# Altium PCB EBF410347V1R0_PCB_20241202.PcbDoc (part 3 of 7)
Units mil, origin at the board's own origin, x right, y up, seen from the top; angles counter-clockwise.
Board outline 5098.43 x 3464.57 mil, 6 copper layers (TOP, GND02, ART03, ART04, PWR05, BOTTOM), stack 47.2 mil thick; 566 components, 452 nets, 1905 pads, 1432 vias.
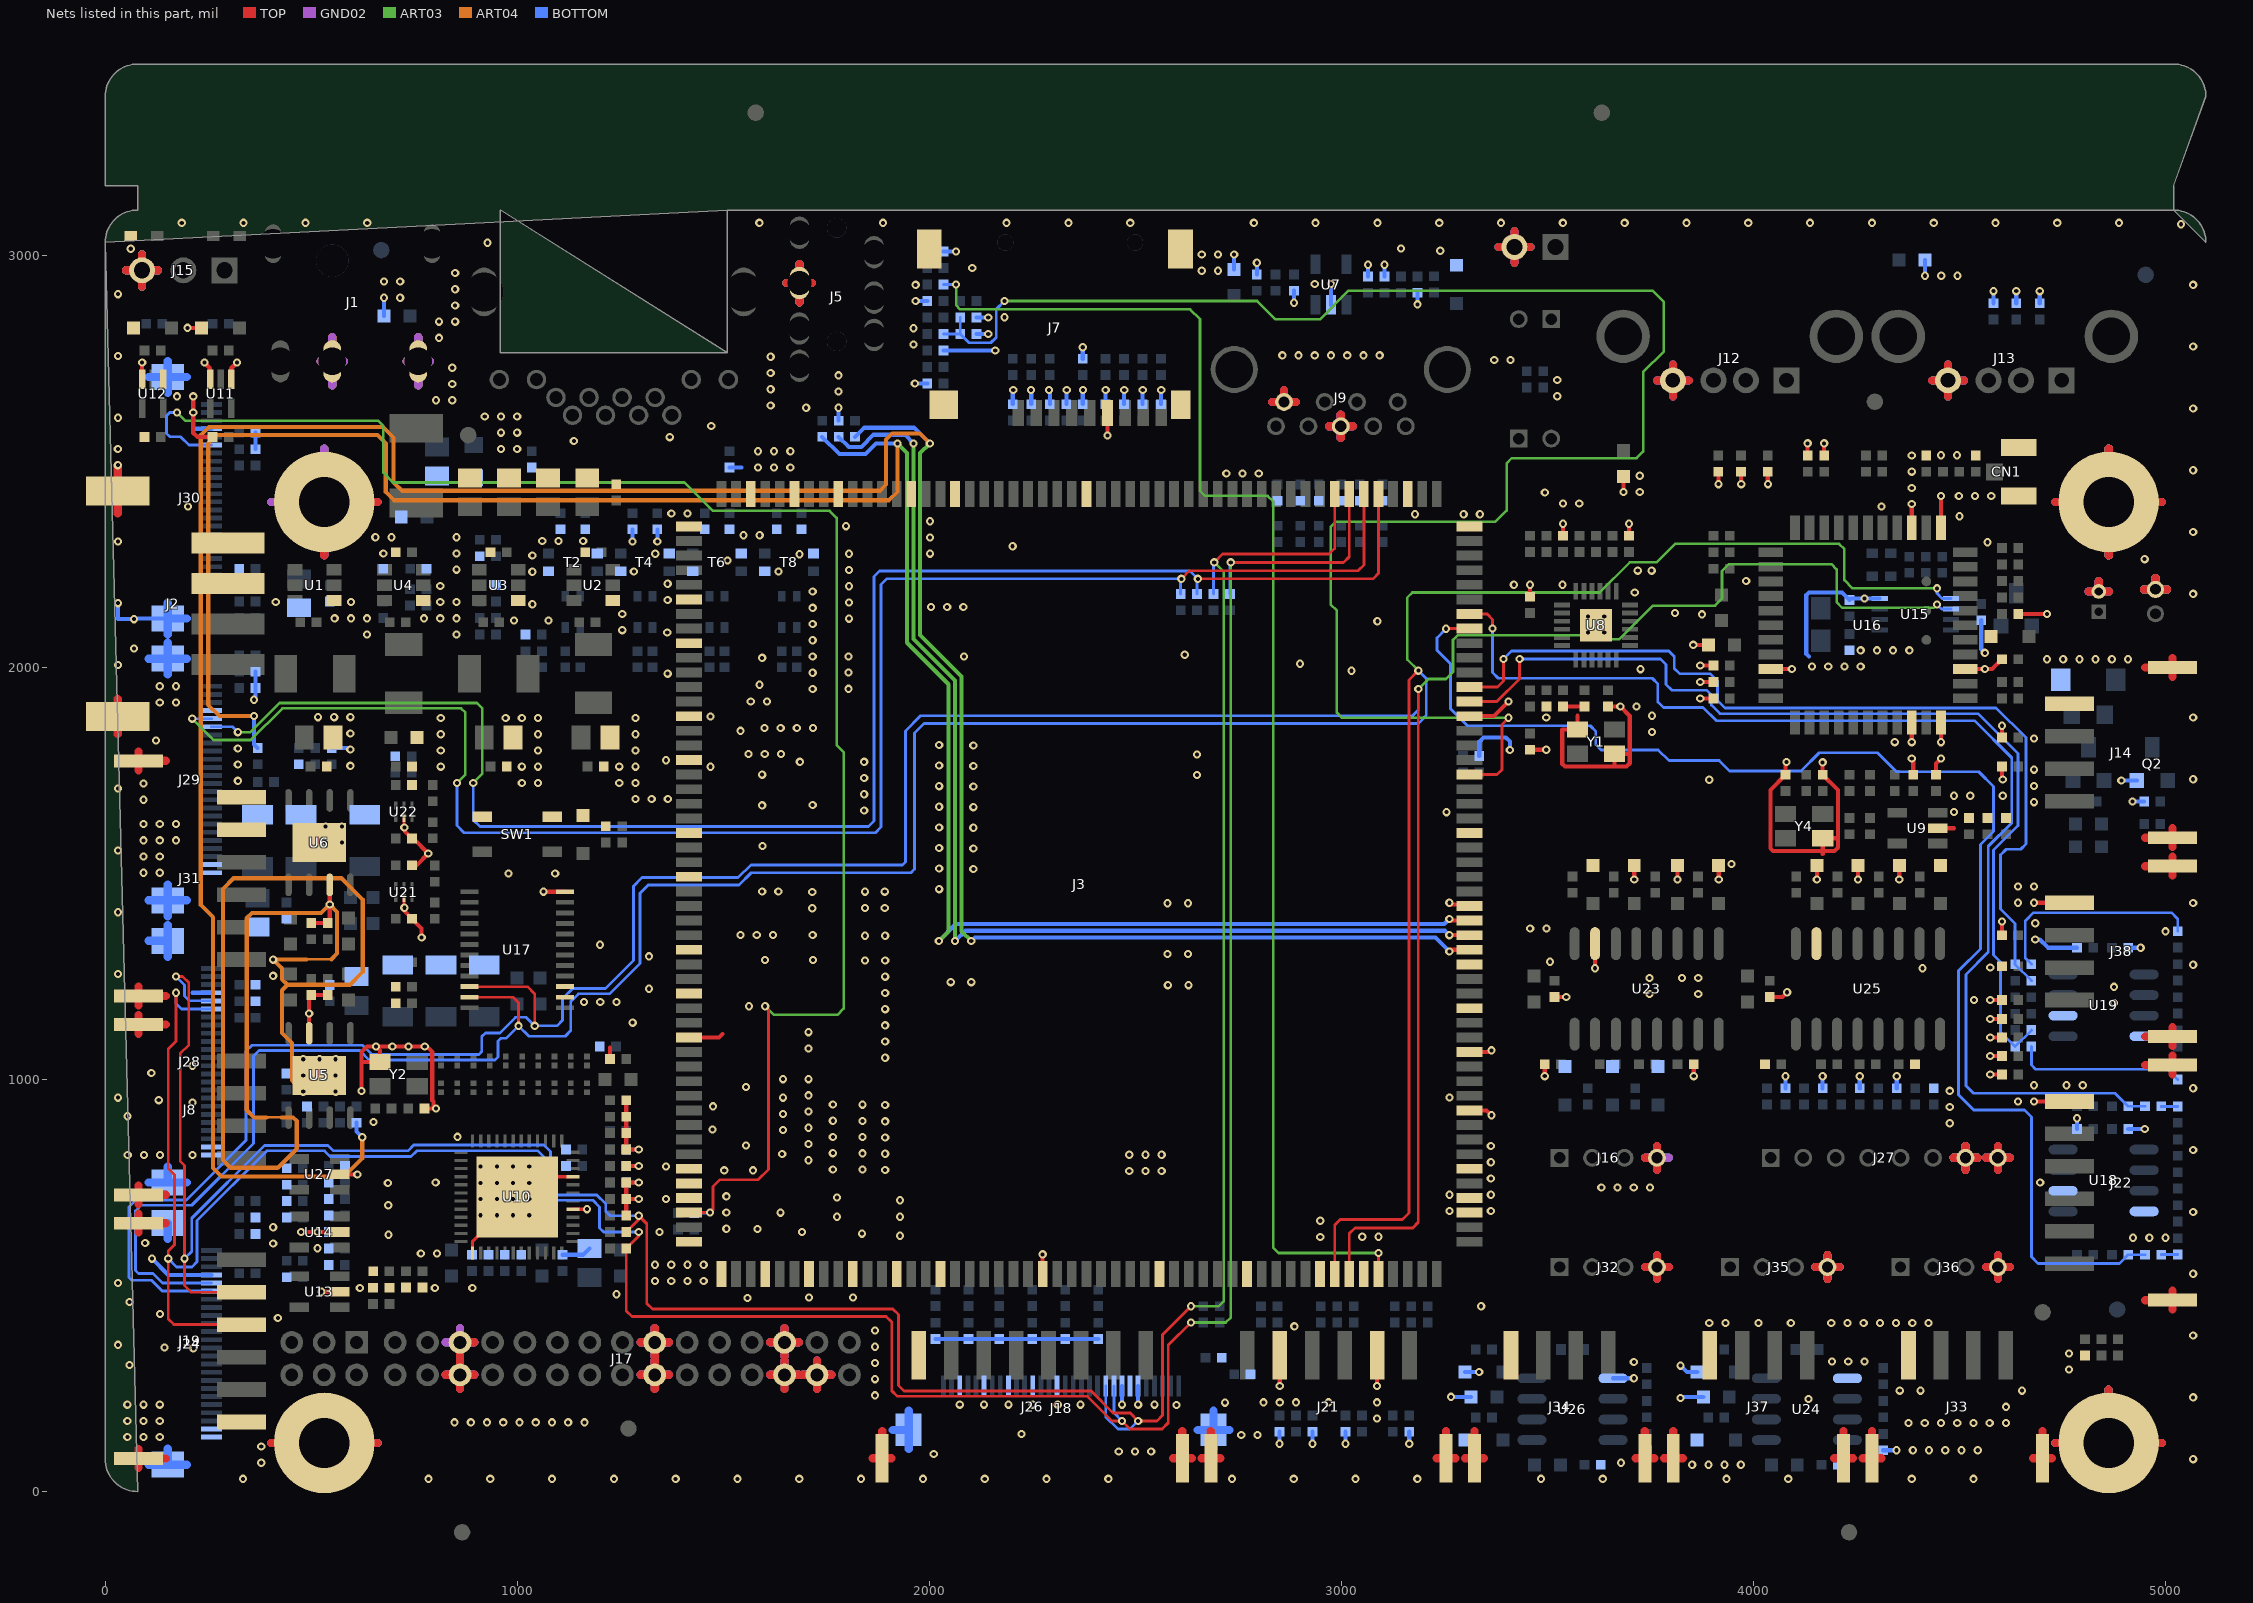
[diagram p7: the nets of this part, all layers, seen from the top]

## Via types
v1: diameter 20, hole 10, TOP to BOTTOM, 1432 vias

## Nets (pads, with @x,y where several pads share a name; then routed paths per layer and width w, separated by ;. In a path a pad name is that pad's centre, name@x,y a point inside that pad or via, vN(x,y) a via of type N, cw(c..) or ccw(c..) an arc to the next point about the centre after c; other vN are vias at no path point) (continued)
GND: C3.2 C4.2 C5.2 C6.2 C7.2 C8.2 C9.2 C13.2 C14.2 C16.2 C17.2 C18.2 C19.2 C20.2 C21.2 C23.2 C24.2 C26.2 C27.2 C28.2 C29.2 C30.2 C31.2 C32.2 C33.2 C35.1 C36.2 C37.2 C38.2 C39.2 C40.2 C41.2 C42.2 C43.2 C44.2 C45.2 C47.1 C48.2 C49.2 C50.2 C51.2 C52.2 C53.2 C62.1 C65.2 C66.2 C67.2 C68.2 C69.2 C70.2 C71.2 C72.2 C73.2 C74.2 C75.2 C76.2 C77.2 C78.2 C79.2 C80.2 C81.2 C82.2 C83.2 C84.2 C85.2 C86.2 C87.2 C88.2 C89.2 C90.2 C91.2 C92.2 C93.2 C94.2 C95.2 C96.2 C97.2 C98.2 C99.2 C100.2 C101.2 C102.2 C103.2 C104.2 C105.2 C106.2 C107.2 C108.2 C109.2 C110.2 C111.2 C112.2 C113.2 C115.2 C116.2 C117.2 C118.2 C119.2 C120.2 C121.2 C122.2 C123.2 C124.2 C125.2 C126.2 C127.2 C128.2 C129.2 C130.2 C131.2 C132.2 C133.2 C134.2 C135.2 C136.2 C137.2 C138.2 C139.2 C140.2 C141.2 C142.2 C143.2 C144.2 C145.2 C146.2 C147.2 C150.2 C153.2 C154.2 C155.2 C156.2 C157.2 C158.2 C159.2 C160.2 C161.2 C162.2 C164.2 C165.2 CN1.2 CN1.3 D1.2 D2.2 D3.2 D4.2 D5.2 D6.2 D7.2 D8.2 D9.1 D10.1 D11.1 D12.1 D13.1 D14.1 D15.1 D16.1 D17.2 D18.2 D19.2 D20.2 D21.2 D22.2 D23.2 D24.2 D25.2 D26.2 D27.2 D28.2 D29.2 D30.2 D31.2 D32.2 D33.2 D34.2 D35.2 D36.2 D37.2 D38.2 D39.2 D40.2 D41.2 D42.2 D44.1 D47.2 D48.2 D49.2 D50.2 D51.2 D52.2 D53.2 D55.2 D56.2 D57.2 D58.2 D59.2 D60.2 D61.2 D62.2 D63.2 D64.2 D65.2 D67.2 D68.2 D69.2 D70.2 D71.2 D72.2 D73.2 D74.2 D75.2 D76.2 J1.2 J1.3 J2.1 J2.2 J2.5 J2.6 J3.3 J3.4 J3.6 J3.10 J3.14 J3.17 J3.20 J3.24 J3.29 J3.37 J3.50 J3.53 J3.75 J3.84 J3.87 J3.92 J3.95 J3.98 J3.101 J3.106 J3.109 J3.114 J3.117 J3.122 J3.125 J3.130 J3.133 J3.136 J3.145 J3.146 J3.147 J3.150 J3.151 J3.154 J3.157 J3.160 J3.163 J3.166 J3.173 J3.181 J3.187 J3.192 J3.195 J5.2 J7.6 J7.10 J7.11 J7.12 J7.13 J8.5 J8.6 J9.4 J9.7 J11.2 J12.4 J13.4 J14.1 J14.5 J14.6 J15.3 J16.4 J17.4 J17.5 J17.6 J17.13 J17.14 J17.25 J17.26 J18.6 J18.7 J18.8 J18.16 J18.19 J18.22 J18.25 J18.28 J18.31 J18.32 J19.1 J19.7 J19.8 J21.2 J21.5 J21.7 J21.8 J22.1 J22.7 J22.8 J23.2 J24.4 J24.23 J24.24 J24.25 J24.26 J25.2 J26.8 J26.9 J26.10 J27.7 J27.8 J28.4 J28.23 J28.24 J28.25 J28.26 J29.4 J29.23 J29.24 J29.25 J29.26 J30.4 J30.23 J30.24 J30.25 J30.26 J31.5 J31.6 J31.7 J31.8 J32.4 J33.4 J33.5 J33.6 J34.4 J34.5 J34.6 J35.4 J36.4 J37.4 J37.5 J37.6 J38.1 J38.5 J38.6 L2.2 L10.1 L11.1 L12.1 LED1.1 Q2.2 R2.2 R4.2 R7.2 R9.2 R11.2 R16.2 R17.2 R27.1 R28.2 R29.2 R38.1 R40.2 R50.2 R51.1 R57.2 R59.2 R66.2 R68.2 R76.1 R77.1 R85.2 R111.2 R112.2 R121.2 R122.2 R129.2 R138.2 R163.2 R173.2 R180.2 R181.2 SS1.1 SS2.1 SS3.1 SS4.1 SW1.3 SW1.4 T2.1 T2.3 T4.1 T4.3 T6.1 T6.3 T8.1 T8.3 U1.1 U2.1 U3.1 U4.1 U5.7 U5.9 U6.7 U6.9 U7.2 U8.25 U9.2 U10.5 U10.9 U10.37 U10.49 U11.1 U11.3 U12.1 U12.3 U13.2 U14.2 U15.4 U16.1 U16.3 U16.20 U16.31 U16.33 U16.36 U17.2 U17.3 U17.12 U18.2 U18.8 U19.2 U19.8 U21.2 U22.2 U23.15 U24.5 U25.15 U26.5 U27.2 Y1.2 Y1.4 Y2.2 Y4.2 | length 35395.2
  TOP w8: U21.2@725,1440.24 725,1418 v1(726,1417) ; U22.2@725,1635.24 725,1613 v1(726,1612) ; U10.37@891.63,579.17 891.63,607.63 911.16,627.16 v1(911.16,670.63) ; v1(1029.27,749.37) 1044.12,764.21 U10.9@1135.73,764.21 ; U10.5@1135.73,685.47 v1(1169.53,685.47)
  TOP w10: v1@30.29,2490.65 v1(30.68,2491.05) ; U12.3@89.72,2699.8 v1(89.72,2740.05) ; v1(200,2824.37) D31.2@233.74,2824.37 ; v1(213.71,2658.03) v1(213.71,2618.66) 213.71,2569.37 223.71,2559.37 C85.2@260.32,2559.37 ; v1(240.94,2740.05) 254.72,2726.28 U11.3@254.72,2699.8 ; U11.1@305.91,2699.8 305.91,2726.28 v1(319.69,2740.05) ; v1(475.63,630) v1(515,630) U14.2@569.21,630 ; U5.7@495,1112.36 v1(495,1160) 495,1200.32 C37.2@500,1205.32 C38.2@540,1205.32 ; C49.2@500,1379.68 C48.2@540,1379.68 545,1384.68 v1(545,1425) U6.7@545,1472.64 ; v1(525,485) U13.2@569.21,485 ; U27.2@569.21,770 611.68,770 v1(612,769.68) ; v1(622,972) 622,1041 ; v1(726,1417) 726,1408.68 C128.2@744.68,1390 768.11,1366.57 v1(768.11,1345) ; v1(726,1612) 726,1603.68 C136.2@744.68,1585 747.74,1585 v1(784.06,1548.68) 755.38,1520 C132.2@744.68,1520 ; R85.2@774.68,930 v1(803,930) 796.48,936.52 796.48,946.57 794.15,948.9 793.87,949.19 793.87,1066.77 780.64,1080 v1(775.63,1080) v1(736.26,1080) v1(696.89,1080) v1(657.52,1080) ; v1(1064,1456) 1064.25,1455.75 U17.12@1116.14,1455.75 ; C111.2@1225.32,1050 1225.32,1077.32 ; R77.1@1264.68,670 R76.1@1264.68,710 ; C89.2@1264.68,790 v1(1295,790) ; C113.2@1264.68,950 C94.2@1264.68,910 C95.2@1264.68,870 C90.2@1264.68,830 v1(1295,830) ; v1(1295,710) R76.1@1264.68,710 ; v1(1295,750) C93.2@1264.68,750 R76.1@1264.68,710 ; J3.136@1416.89,1102.32 1489.72,1102.32 1498.34,1110.94 ; J3.173@2275.16,527.52 v1(2275.16,575.84) ; v1(2432.68,2563) J7.6@2432.68,2618.11 ; v1(2850.55,256) J21.5@2850.55,331.1 ; v1(3086.77,256) J21.2@3086.77,331.1 ; v1(3262.21,1429.16) 3266.15,1425.22 3306.59,1425.22 J3.24@3310.59,1421.22 ; J3.10@3310.59,925.16 3352.73,925.16 v1(3364.54,913.35) ; J3.14@3310.59,1066.89 3360.61,1066.89 v1(3364.54,1070.83) ; J3.37@3310.59,1881.85 3370.22,1881.85 v1(3405.65,1917.28) ; C68.2@3458.11,1800.32 v1(3497.43,1800.31) ; C71.2@3458.11,2171.45 v1(3458.11,2200.77) ; v1(3493.75,1008.16) C146.2@3493.75,1037 ; C144.2@3517.11,1200.32 v1(3545.79,1200.32) ; C70.2@3538.11,1905.32 C73.2@3590.11,1905.32 ; C72.2@3538.11,2319.68 v1(3538.11,2349) ; 3573.11,1883 3572.83,1882.72 Y1.4@3572.83,1849.53 3536.77,1849.53 3536.24,1849 3536.24,1766.23 3542.69,1759.79 3664.11,1759.79 ; v1(3615.91,1270.2) U23.15@3615.91,1329.8 ; C74.2@3647.11,1905.32 v1(3677.11,1905.32) 3699.98,1882.45 3699.98,1791 ; v1(3685,2426) L11.1@3685,2463.5 ; R66.2@3698.11,2319.68 v1(3698.11,2349) ; v1(3710.91,1485.52) D65.2@3710.91,1519.26 ; v1(3815.91,1485.52) D63.2@3815.91,1519.26 ; v1(3854.11,2055) C126.2@3891.61,2055 ; v1(3855.27,1008.16) C147.2@3855.27,1037 ; v1(3871.11,1925) C124.2@3903.43,1925 ; v1(3871.11,1965) C125.2@3903.43,1965 ; v1(3871.11,2005) C127.2@3903.43,2005 ; D25.2@3915,2475.32 3915,2445.63 v1(3915.63,2445) ; v1(3915.91,1485.52) D62.2@3915.91,1519.26 ; D24.2@3970,2475.32 3970,2445.63 v1(3970.63,2445) ; C80.2@4035,2475.32 4035,2445.63 v1(4035.63,2445) ; C150.2@4040,1200.32 4070.32,1200.32 v1(4082,1212) ; U16.20@4041.89,1996.26 v1(4093.37,1996.26) ; v1(4080.11,1770.45) 4080.11,1769.88 4078.11,1767.88 C123.2@4078.11,1739.68 4041.24,1702.81 4041.24,1561.23 4047.69,1554.79 4197.12,1554.79 4204.98,1562.64 4204.98,1585 ; C121.2@4131.81,2514.68 v1(4131.81,2544) ; v1(4154.11,1485.52) D71.2@4154.11,1519.26 ; 4168.11,1547 4168.39,1547.28 Y4.2@4168.39,1585.47 4204.51,1585.47 4204.98,1585 ; v1(4168.11,1769.88) R163.2@4168.11,1739.68 4204.98,1702.81 4204.98,1585 ; C122.2@4171.81,2514.68 v1(4171.81,2544) ; v1(4254.11,1485.52) D72.2@4254.11,1519.26 ; v1(4354.11,1485.52) D70.2@4354.11,1519.26 ; v1(4384.41,1779.45) 4388.11,1775.75 C77.2@4388.11,1739.68 ; v1(4384.41,1818.82) U16.31@4384.41,1866.34 ; U16.3@4384.41,2338.78 v1(4384.41,2396.53) ; R68.2@4443.11,1739.68 4443.11,1767.28 v1(4455.28,1779.45) ; U9.2@4447.32,1610 4487.11,1610 ; v1(4455.28,1818.82) U16.33@4455.28,1866.34 ; U16.1@4455.28,2338.78 v1(4455.28,2416) ; U16.36@4514.33,1996.26 v1(4561.85,1996.26) 4579.69,1996.26 C116.2@4603.43,2020 ; v1(4575,1012) D35.2@4603.43,1012 ; v1(4575,1057) D36.2@4603.43,1057 ; v1(4575,1102) D37.2@4603.43,1102 ; v1(4575,1147) D74.2@4603.43,1147 ; v1(4575,1192.99) C137.2@4603.43,1192.99 ; D73.2@4603.43,1350 v1(4603.43,1383.32) ; D28.2@4603.43,1760 4603.43,1729.9 v1(4605.22,1728.11) ; D29.2@4603.43,1830 v1(4603.43,1858.68) ; R129.2@4642.79,2130 v1(4712.48,2130) ; v1(4681.34,946.77) J22.1@4767.41,946.77 ; v1(4681.34,1429.21) J38.1@4767.41,1429.21 ; 622,1041 623.53,1042.53 Y2.2@666.72,1042.53 666.72,1070.8 v1(657.52,1080) ; 622,1041 622,1067 635,1080 v1(657.52,1080) ; 3664.11,1759.79 3692.12,1759.79 3699.98,1767.64 3699.98,1791 ; 3664.11,1759.79 3663.39,1760.51 Y1.2@3663.39,1790.47 3699.45,1790.47 3699.98,1791
  TOP w20: 30.29,1838.9 J2.6@30.29,1881.34 30.29,1923.78 ; 30.29,2373.71 J2.5@30.29,2428.59 v1@30.29,2490.65 ; 51.12,2964.05 J15.3@89.61,2964.05 ; 80.71,57.64 J19.8@80.71,80.39 ; 80.71,103.15 J19.8@80.71,80.39 ; 80.71,628.51 J19.7@80.71,651.26 ; 80.71,674.01 J19.7@80.71,651.26 ; 80.71,697.56 J8.6@80.71,720.32 ; 80.71,743.07 J8.6@80.71,720.32 ; 80.71,1110.95 J8.5@80.71,1133.7 ; 80.71,1156.45 J8.5@80.71,1133.7 ; 80.71,1180 J31.8@80.71,1202.76 ; 80.71,1225.51 J31.8@80.71,1202.76 ; 80.71,1750.87 J31.7@80.71,1773.62 ; 80.71,1796.37 J31.7@80.71,1773.62 ; 89.61,2925.55 J15.3@89.61,2964.05 ; 89.61,3002.55 J15.3@89.61,2964.05 ; 128.11,2964.05 J15.3@89.61,2964.05 ; 146.76,80.39 J19.8@80.71,80.39 ; 146.76,651.26 J19.7@80.71,651.26 ; 146.76,720.32 J8.6@80.71,720.32 ; 146.76,1133.7 J8.5@80.71,1133.7 ; 146.76,1202.76 J31.8@80.71,1202.76 ; 146.76,1773.62 J31.7@80.71,1773.62 ; 402.45,118.11 SS1.1@531.5,118.11 660.54,118.11 ; 531.5,2272.52 SS4.1@531.5,2401.57 660.55,2401.57 ; 826.74,283.46 J17.26@861.3,283.46 ; 861.3,248.9 J17.26@861.3,283.46 ; 861.3,318.03 J17.26@861.3,283.46 ; 861.3,327.64 J17.25@861.3,362.2 895.86,362.2 ; 895.86,283.46 J17.26@861.3,283.46 ; 1299.18,283.46 J17.14@1333.74,283.46 ; 1299.18,362.2 J17.13@1333.74,362.2 ; 1333.74,248.9 J17.14@1333.74,283.46 ; 1333.74,318.03 J17.14@1333.74,283.46 ; 1333.74,327.64 J17.13@1333.74,362.2 ; 1333.74,396.77 J17.13@1333.74,362.2 ; 1368.3,283.46 J17.14@1333.74,283.46 ; 1368.3,362.2 J17.13@1333.74,362.2 ; 1614.14,283.46 J17.6@1648.7,283.46 ; 1614.14,362.2 J17.5@1648.7,362.2 ; 1648.7,248.9 J17.6@1648.7,283.46 ; 1648.7,318.03 J17.6@1648.7,283.46 ; 1648.7,327.64 J17.5@1648.7,362.2 ; 1648.7,396.77 J17.5@1648.7,362.2 ; 1654.26,2933.07 J5.2@1684.88,2933.07 ; 1683.26,283.46 J17.6@1648.7,283.46 ; 1683.26,362.2 J17.5@1648.7,362.2 ; 1684.88,2886.7 J5.2@1684.88,2933.07 ; 1684.88,2979.44 J5.2@1684.88,2933.07 ; 1692.88,283.46 J17.4@1727.44,283.46 ; 1715.5,2933.07 J5.2@1684.88,2933.07 ; 1727.44,248.9 J17.4@1727.44,283.46 ; 1727.44,318.03 J17.4@1727.44,283.46 ; 1762,283.46 J17.4@1727.44,283.46 ; 1863.08,81.1 J26.9@1885.83,81.1 ; 1885.83,147.16 J26.9@1885.83,81.1 ; 1908.58,81.1 J26.9@1885.83,81.1 ; 2591.42,81.1 J26.10@2614.17,81.1 ; 2614.17,147.16 J26.10@2614.17,81.1 ; 2636.93,81.1 J26.10@2614.17,81.1 ; 2660.48,81.1 J21.7@2683.23,81.1 ; 2683.23,147.16 J21.7@2683.23,81.1 ; 2705.98,81.1 J21.7@2683.23,81.1 ; 2832.4,2644.5 J9.4@2861.05,2644.5 ; 2861.05,2673.16 J9.4@2861.05,2644.5 ; 2889.71,2644.5 J9.4@2861.05,2644.5 ; 2970.19,2585.45 J9.7@2998.85,2585.45 ; 2998.85,2556.79 J9.7@2998.85,2585.45 ; 2998.85,2614.11 J9.7@2998.85,2585.45 ; 3027.51,2585.45 J9.7@2998.85,2585.45 ; 3231.34,81.1 J21.8@3254.09,81.1 ; 3254.09,147.16 J21.8@3254.09,81.1 ; 3276.85,81.1 J21.8@3254.09,81.1 ; 3300.4,81.1 J34.5@3323.15,81.1 ; 3323.15,147.16 J34.5@3323.15,81.1 ; 3345.9,81.1 J34.5@3323.15,81.1 ; 3381.5,3020.55 J11.2@3420,3020.55 ; 3420,2982.05 J11.2@3420,3020.55 ; 3420,3059.05 J11.2@3420,3020.55 ; 3458.5,3020.55 J11.2@3420,3020.55 ; 3713.78,81.1 J34.6@3736.54,81.1 ; 3736.54,147.16 J34.6@3736.54,81.1 ; 3737.41,545 J32.4@3766.06,545 ; 3737.41,810 J16.4@3766.06,810 ; 3759.29,81.1 J34.6@3736.54,81.1 ; 3766.06,516.34 J32.4@3766.06,545 ; 3766.06,573.66 J32.4@3766.06,545 ; 3766.06,781.34 J16.4@3766.06,810 ; 3766.06,838.66 J16.4@3766.06,810 ; 3766.3,2696.85 J12.4@3804.8,2696.85 ; 3782.84,81.1 J37.5@3805.59,81.1 ; 3794.72,545 J32.4@3766.06,545 ; 3804.8,2658.35 J12.4@3804.8,2696.85 ; 3804.8,2735.35 J12.4@3804.8,2696.85 ; 3805.59,147.16 J37.5@3805.59,81.1 ; 3828.34,81.1 J37.5@3805.59,81.1 ; 3843.3,2696.85 J12.4@3804.8,2696.85 ; 4151.11,545 J35.4@4179.77,545 ; 4179.77,516.34 J35.4@4179.77,545 ; 4179.77,573.66 J35.4@4179.77,545 ; 4196.23,81.1 J37.6@4218.98,81.1 ; 4208.42,545 J35.4@4179.77,545 ; 4218.98,147.16 J37.6@4218.98,81.1 ; 4241.73,81.1 J37.6@4218.98,81.1 ; 4265.28,81.1 J33.5@4288.03,81.1 ; 4288.03,147.16 J33.5@4288.03,81.1 ; 4310.78,81.1 J33.5@4288.03,81.1 ; 4433.94,2696.85 J13.4@4472.44,2696.85 ; 4472.44,2658.35 J13.4@4472.44,2696.85 ; 4472.44,2735.35 J13.4@4472.44,2696.85 ; 4486.07,810 J27.7@4514.73,810 ; 4510.94,2696.85 J13.4@4472.44,2696.85 ; 4514.73,781.34 J27.7@4514.73,810 ; 4514.73,838.66 J27.7@4514.73,810 ; 4543.38,810 J27.7@4514.73,810 ; 4564.81,545 J36.4@4593.47,545 ; 4564.81,810 J27.8@4593.47,810 ; 4593.47,516.34 J36.4@4593.47,545 ; 4593.47,573.66 J36.4@4593.47,545 ; 4593.47,781.34 J27.8@4593.47,810 ; 4593.47,838.66 J27.8@4593.47,810 ; 4622.12,545 J36.4@4593.47,545 ; 4622.12,810 J27.8@4593.47,810 ; 4678.66,81.1 J33.6@4701.42,81.1 ; 4701.42,147.16 J33.6@4701.42,81.1 ; 4724.17,81.1 J33.6@4701.42,81.1 ; 4733.16,118.11 SS2.1@4862.2,118.11 ; 4733.16,2401.57 SS3.1@4862.21,2401.57 ; 4813.39,2184.57 J23.2@4838.11,2184.57 ; 4838.11,2209.29 J23.2@4838.11,2184.57 ; 4862.2,247.16 SS2.1@4862.2,118.11 ; 4862.21,2272.52 SS3.1@4862.21,2401.57 ; 4862.21,2530.62 SS3.1@4862.21,2401.57 ; 4862.83,2184.57 J23.2@4838.11,2184.57 ; 4948.24,2189.53 J25.2@4975.91,2189.53 ; 4951.35,464.48 J22.7@5017.41,464.48 ; 4951.35,1035.35 J22.8@5017.41,1035.35 ; 4951.35,1104.4 J38.5@5017.41,1104.4 ; 4951.35,1517.79 J38.6@5017.41,1517.79 ; 4951.35,1586.85 J14.5@5017.41,1586.85 ; 4951.35,2000.23 J14.6@5017.41,2000.23 ; 4975.91,2217.2 J25.2@4975.91,2189.53 ; 4991.25,118.11 SS2.1@4862.2,118.11 ; 4991.26,2401.57 SS3.1@4862.21,2401.57 ; 5003.58,2189.53 J25.2@4975.91,2189.53 ; 5017.41,441.73 J22.7@5017.41,464.48 ; 5017.41,487.24 J22.7@5017.41,464.48 ; 5017.41,1012.6 J22.8@5017.41,1035.35 ; 5017.41,1058.1 J22.8@5017.41,1035.35 ; 5017.41,1081.65 J38.5@5017.41,1104.4 ; 5017.41,1127.16 J38.5@5017.41,1104.4 ; 5017.41,1495.04 J38.6@5017.41,1517.79 ; 5017.41,1540.54 J38.6@5017.41,1517.79 ; 5017.41,1564.09 J14.5@5017.41,1586.85 ; 5017.41,1609.6 J14.5@5017.41,1586.85 ; 5017.41,1977.48 J14.6@5017.41,2000.23 ; 5017.41,2022.98 J14.6@5017.41,2000.23
  GND02 w20: 51.12,2964.05 J15.3@89.61,2964.05 ; 89.61,2925.55 J15.3@89.61,2964.05 ; 89.61,3002.55 J15.3@89.61,2964.05 ; 128.11,2964.05 J15.3@89.61,2964.05 ; 402.45,118.11 SS1.1@531.5,118.11 660.54,118.11 ; 402.45,2401.57 SS4.1@531.5,2401.57 ; 522.53,2743.11 J1.2@551.18,2743.11 ; 531.5,2272.52 SS4.1@531.5,2401.57 ; 531.5,2530.62 SS4.1@531.5,2401.57 ; 551.18,2684.91 J1.2@551.18,2743.11 ; 551.18,2801.31 J1.2@551.18,2743.11 ; 579.83,2743.11 J1.2@551.18,2743.11 ; 660.55,2401.57 SS4.1@531.5,2401.57 ; 731.13,2743.11 J1.3@759.78,2743.11 ; 759.78,2684.91 J1.3@759.78,2743.11 ; 759.78,2801.31 J1.3@759.78,2743.11 ; 788.43,2743.11 J1.3@759.78,2743.11 ; 826.74,283.46 J17.26@861.3,283.46 ; 826.74,362.2 J17.25@861.3,362.2 ; 861.3,248.9 J17.26@861.3,283.46 ; 861.3,318.03 J17.26@861.3,283.46 ; 861.3,327.64 J17.25@861.3,362.2 ; 861.3,396.77 J17.25@861.3,362.2 ; 895.86,283.46 J17.26@861.3,283.46 ; 895.86,362.2 J17.25@861.3,362.2 ; 1299.18,283.46 J17.14@1333.74,283.46 ; 1299.18,362.2 J17.13@1333.74,362.2 ; 1333.74,248.9 J17.14@1333.74,283.46 ; 1333.74,318.03 J17.14@1333.74,283.46 ; 1333.74,327.64 J17.13@1333.74,362.2 ; 1333.74,396.77 J17.13@1333.74,362.2 ; 1368.3,283.46 J17.14@1333.74,283.46 ; 1368.3,362.2 J17.13@1333.74,362.2 ; 1614.14,283.46 J17.6@1648.7,283.46 ; 1614.14,362.2 J17.5@1648.7,362.2 ; 1648.7,248.9 J17.6@1648.7,283.46 ; 1648.7,318.03 J17.6@1648.7,283.46 ; 1648.7,327.64 J17.5@1648.7,362.2 ; 1648.7,396.77 J17.5@1648.7,362.2 ; 1654.26,2933.07 J5.2@1684.88,2933.07 ; 1683.26,283.46 J17.6@1648.7,283.46 ; 1683.26,362.2 J17.5@1648.7,362.2 ; 1684.88,2886.7 J5.2@1684.88,2933.07 ; 1684.88,2979.44 J5.2@1684.88,2933.07 ; 1692.88,283.46 J17.4@1727.44,283.46 ; 1715.5,2933.07 J5.2@1684.88,2933.07 ; 1727.44,248.9 J17.4@1727.44,283.46 ; 1727.44,318.03 J17.4@1727.44,283.46 ; 1762,283.46 J17.4@1727.44,283.46 ; 2832.4,2644.5 J9.4@2861.05,2644.5 ; 2861.05,2673.16 J9.4@2861.05,2644.5 ; 2889.71,2644.5 J9.4@2861.05,2644.5 ; 2970.19,2585.45 J9.7@2998.85,2585.45 ; 2998.85,2556.79 J9.7@2998.85,2585.45 ; 2998.85,2614.11 J9.7@2998.85,2585.45 ; 3027.51,2585.45 J9.7@2998.85,2585.45 ; 3381.5,3020.55 J11.2@3420,3020.55 ; 3420,2982.05 J11.2@3420,3020.55 ; 3420,3059.05 J11.2@3420,3020.55 ; 3458.5,3020.55 J11.2@3420,3020.55 ; 3737.41,545 J32.4@3766.06,545 ; 3737.41,810 J16.4@3766.06,810 ; 3766.06,516.34 J32.4@3766.06,545 ; 3766.06,573.66 J32.4@3766.06,545 ; 3766.06,781.34 J16.4@3766.06,810 ; 3766.06,838.66 J16.4@3766.06,810 ; 3766.3,2696.85 J12.4@3804.8,2696.85 ; 3794.72,545 J32.4@3766.06,545 ; 3794.72,810 J16.4@3766.06,810 ; 3804.8,2658.35 J12.4@3804.8,2696.85 ; 3804.8,2735.35 J12.4@3804.8,2696.85 ; 3843.3,2696.85 J12.4@3804.8,2696.85 ; 4151.11,545 J35.4@4179.77,545 ; 4179.77,516.34 J35.4@4179.77,545 ; 4179.77,573.66 J35.4@4179.77,545 ; 4208.42,545 J35.4@4179.77,545 ; 4433.94,2696.85 J13.4@4472.44,2696.85 ; 4472.44,2658.35 J13.4@4472.44,2696.85 ; 4472.44,2735.35 J13.4@4472.44,2696.85 ; 4486.07,810 J27.7@4514.73,810 ; 4510.94,2696.85 J13.4@4472.44,2696.85 ; 4514.73,781.34 J27.7@4514.73,810 ; 4514.73,838.66 J27.7@4514.73,810 ; 4543.38,810 J27.7@4514.73,810 ; 4564.81,545 J36.4@4593.47,545 ; 4564.81,810 J27.8@4593.47,810 ; 4593.47,516.34 J36.4@4593.47,545 ; 4593.47,573.66 J36.4@4593.47,545 ; 4593.47,781.34 J27.8@4593.47,810 ; 4593.47,838.66 J27.8@4593.47,810 ; 4622.12,545 J36.4@4593.47,545 ; 4622.12,810 J27.8@4593.47,810 ; 4733.16,118.11 SS2.1@4862.2,118.11 ; 4733.16,2401.57 SS3.1@4862.21,2401.57 ; 4813.39,2184.57 J23.2@4838.11,2184.57 ; 4838.11,2209.29 J23.2@4838.11,2184.57 ; 4862.2,247.16 SS2.1@4862.2,118.11 ; 4862.21,2272.52 SS3.1@4862.21,2401.57 ; 4862.21,2530.62 SS3.1@4862.21,2401.57 ; 4862.83,2184.57 J23.2@4838.11,2184.57 ; 4948.24,2189.53 J25.2@4975.91,2189.53 ; 4975.91,2217.2 J25.2@4975.91,2189.53 ; 4991.25,118.11 SS2.1@4862.2,118.11 ; 4991.26,2401.57 SS3.1@4862.21,2401.57 ; 5003.58,2189.53 J25.2@4975.91,2189.53
  ART03 w20: 51.12,2964.05 J15.3@89.61,2964.05 ; 89.61,2925.55 J15.3@89.61,2964.05 ; 89.61,3002.55 J15.3@89.61,2964.05 ; 128.11,2964.05 J15.3@89.61,2964.05 ; 402.45,118.11 SS1.1@531.5,118.11 660.54,118.11 ; 522.53,2743.11 J1.2@551.18,2743.11 ; 551.18,2684.91 J1.2@551.18,2743.11 ; 579.83,2743.11 J1.2@551.18,2743.11 ; 759.78,2684.91 J1.3@759.78,2743.11 ; 759.78,2801.31 J1.3@759.78,2743.11 ; 788.43,2743.11 J1.3@759.78,2743.11 ; 1654.26,2933.07 J5.2@1684.88,2933.07 ; 1684.88,2886.7 J5.2@1684.88,2933.07 ; 1684.88,2979.44 J5.2@1684.88,2933.07 ; 1715.5,2933.07 J5.2@1684.88,2933.07 ; 3381.5,3020.55 J11.2@3420,3020.55 ; 3420,2982.05 J11.2@3420,3020.55 ; 3420,3059.05 J11.2@3420,3020.55 ; 3458.5,3020.55 J11.2@3420,3020.55 ; 3737.41,545 J32.4@3766.06,545 ; 3737.41,810 J16.4@3766.06,810 ; 3766.06,516.34 J32.4@3766.06,545 ; 3766.06,573.66 J32.4@3766.06,545 ; 3766.06,781.34 J16.4@3766.06,810 ; 3766.06,838.66 J16.4@3766.06,810 ; 3794.72,545 J32.4@3766.06,545 ; 3794.72,810 J16.4@3766.06,810 ; 4151.11,545 J35.4@4179.77,545 ; 4179.77,516.34 J35.4@4179.77,545 ; 4179.77,573.66 J35.4@4179.77,545 ; 4208.42,545 J35.4@4179.77,545 ; 4433.94,2696.85 J13.4@4472.44,2696.85 ; 4472.44,2658.35 J13.4@4472.44,2696.85 ; 4472.44,2735.35 J13.4@4472.44,2696.85 ; 4486.07,810 J27.7@4514.73,810 ; 4510.94,2696.85 J13.4@4472.44,2696.85 ; 4514.73,781.34 J27.7@4514.73,810 ; 4514.73,838.66 J27.7@4514.73,810 ; 4543.38,810 J27.7@4514.73,810 ; 4564.81,545 J36.4@4593.47,545 ; 4564.81,810 J27.8@4593.47,810 ; 4593.47,516.34 J36.4@4593.47,545 ; 4593.47,573.66 J36.4@4593.47,545 ; 4593.47,781.34 J27.8@4593.47,810 ; 4593.47,838.66 J27.8@4593.47,810 ; 4622.12,545 J36.4@4593.47,545 ; 4622.12,810 J27.8@4593.47,810 ; 4733.16,118.11 SS2.1@4862.2,118.11 ; 4733.16,2401.57 SS3.1@4862.21,2401.57 ; 4813.39,2184.57 J23.2@4838.11,2184.57 ; 4838.11,2209.29 J23.2@4838.11,2184.57 ; 4862.2,247.16 SS2.1@4862.2,118.11 ; 4862.21,2272.52 SS3.1@4862.21,2401.57 ; 4862.21,2530.62 SS3.1@4862.21,2401.57 ; 4862.83,2184.57 J23.2@4838.11,2184.57 ; 4948.24,2189.53 J25.2@4975.91,2189.53 ; 4975.91,2217.2 J25.2@4975.91,2189.53 ; 4991.25,118.11 SS2.1@4862.2,118.11 ; 4991.26,2401.57 SS3.1@4862.21,2401.57 ; 5003.58,2189.53 J25.2@4975.91,2189.53
  ART04 w6: 392,908 428,908 ; 488.3,1291 489.3,1292 549.5,1292
  ART04 w10: 392,908 361,908 343.5,925.5 343.5,1391.5 356,1404 524,1404 v1(545,1425) 563,1407 563,1305.5 549.5,1292 ; 428,908 456,908 465,899 465,832 418.9,785.9 304.1,785.9 285.5,804.5 285.5,1462.36 311.64,1488.5 573.5,1488.5 625,1437 625,1261 594,1230 442,1230 ; v1(480.63,970.63) 453,998.26 453,1088.24 428.72,1112.52 428.72,1216.72 442,1230 ; 488.3,1291 v1(407.72,1291) 428.72,1270 428.72,1243.28 442,1230
  ART04 w20: 51.12,2964.05 J15.3@89.61,2964.05 ; 89.61,2925.55 J15.3@89.61,2964.05 ; 89.61,3002.55 J15.3@89.61,2964.05 ; 128.11,2964.05 J15.3@89.61,2964.05 ; 402.45,118.11 SS1.1@531.5,118.11 660.54,118.11 ; 402.45,2401.57 SS4.1@531.5,2401.57 ; 522.53,2743.11 J1.2@551.18,2743.11 ; 531.5,2530.62 SS4.1@531.5,2401.57 ; 551.18,2684.91 J1.2@551.18,2743.11 ; 551.18,2801.31 J1.2@551.18,2743.11 ; 579.83,2743.11 J1.2@551.18,2743.11 ; 660.55,2401.57 SS4.1@531.5,2401.57 ; 731.13,2743.11 J1.3@759.78,2743.11 ; 759.78,2684.91 J1.3@759.78,2743.11 ; 759.78,2801.31 J1.3@759.78,2743.11 ; 788.43,2743.11 J1.3@759.78,2743.11 ; 1654.26,2933.07 J5.2@1684.88,2933.07 ; 1684.88,2886.7 J5.2@1684.88,2933.07 ; 1684.88,2979.44 J5.2@1684.88,2933.07 ; 1715.5,2933.07 J5.2@1684.88,2933.07 ; 4151.11,545 J35.4@4179.77,545 ; 4179.77,516.34 J35.4@4179.77,545 ; 4179.77,573.66 J35.4@4179.77,545 ; 4208.42,545 J35.4@4179.77,545 ; 4486.07,810 J27.7@4514.73,810 ; 4514.73,781.34 J27.7@4514.73,810 ; 4514.73,838.66 J27.7@4514.73,810 ; 4543.38,810 J27.7@4514.73,810 ; 4733.16,118.11 SS2.1@4862.2,118.11 ; 4862.2,247.16 SS2.1@4862.2,118.11 ; 4862.21,2272.52 SS3.1@4862.21,2401.57 ; 4862.21,2530.62 SS3.1@4862.21,2401.57 ; 4948.24,2189.53 J25.2@4975.91,2189.53 ; 4975.91,2217.2 J25.2@4975.91,2189.53 ; 4991.25,118.11 SS2.1@4862.2,118.11 ; 4991.26,2401.57 SS3.1@4862.21,2401.57 ; 5003.58,2189.53 J25.2@4975.91,2189.53
  BOTTOM w10: v1@30.68,2156.68 30.68,2117.31 v1(70.06,2117.31) 71.41,2118.66 J30.25@151.53,2118.66 ; v1(113.63,565.28) 153,525.91 J24.4@257.91,525.91 ; 212,1210.7 J28.4@257.91,1210.7 ; 213.71,2579.29 J30.4@257.91,2579.29 ; v1(361.26,1921.85) 364.68,1925.27 C135.2@364.68,1950 C134.2@364.68,1990 ; C131.2@364.68,2530 C133.2@364.68,2570 ; C51.2@550,1804.68 591.06,1804.68 v1(595,1800.74) ; L2.2@676.5,2853 v1(676.5,2897.5) ; C98.2@1110,574.68 1159.64,574.68 C99.2@1175,590.04 ; C92.2@1264.68,750 v1(1295,750) ; C87.2@1264.68,790 v1(1295,790) ; C88.2@1264.68,830 v1(1295,830) ; v1(1280,2306) D11.1@1280,2335.32 ; v1(1340,2306) D12.1@1340,2335.32 ; R50.2@1515,2485.32 1544.68,2485.32 ; R38.1@1780,2599.05 v1(1780,2630.37) ; v1(1965,2689.37) R27.1@1995.32,2689.37 ; v1(1967,2889.37) C33.2@1995.32,2889.37 ; D48.2@2015,370.32 D49.2@2095,370.32 D50.2@2170,370.32 D51.2@2250,370.32 D52.2@2330,370.32 D53.2@2410,370.32 ; C36.2@2034.68,2769.37 v1(2160,2769.37) ; C50.2@2034.68,3009.37 v1(2065,3009.37) ; C40.2@2114.68,2809.37 v1(2143,2809.37) ; R29.2@2114.68,2849.37 v1(2143,2849.37) ; D7.2@2202.61,2639.05 2202.61,2672.07 v1(2203.76,2673.22) ; v1(2247.07,2673.22) 2247.61,2672.68 D6.2@2247.61,2639.05 ; v1(2290.37,2673.22) 2292.61,2670.98 D5.2@2292.61,2639.05 ; D8.2@2332.61,2639.05 2332.61,2672.15 v1(2333.68,2673.22) ; C53.2@2372.61,2639.05 2372.61,2672.78 v1(2373.05,2673.22) ; C52.2@2372.61,2749.05 v1(2372.61,2777.37) ; D4.2@2427.61,2639.05 2427.61,2672.78 v1(2428.05,2673.22) ; v1(2467.63,210.93) J18.8@2467.63,255.91 ; D3.2@2472.61,2639.05 2472.61,2672.78 v1(2473.05,2673.22) ; v1(2507,210.93) J18.6@2507,255.91 ; D2.2@2517.61,2639.05 2517.61,2672.78 v1(2518.05,2673.22) ; D1.2@2562.61,2639.05 2562.61,2672.78 v1(2563.05,2673.22) ; L10.1@2740,2965.87 v1(2740,3002.37) ; R57.2@2795,2954.05 v1(2795,2982.37) ; v1(2850,116) D41.2@2850,145.32 ; v1(2885,2885.37) C65.2@2885,2914.69 ; v1(2930,116) D42.2@2930,145.32 ; U7.2@2975,2880.16 v1(2975,2930.94) ; v1(3010,116) D40.2@3010,145.32 ; C66.2@3065,2949.05 v1(3065,2977.37) ; C67.2@3105,2949.05 v1(3105,2977.37) ; v1(3165,116) D39.2@3165,145.32 ; v1(3185,2881.37) R59.2@3185,2909.69 ; v1(3266,230) R121.2@3314.5,230 ; D68.2@3299.74,290 v1(3334.48,290) ; R173.2@3334.68,1785 3334.68,1819.68 3345,1830 3399,1830 3409,1820 v1(3409,1800) ; U26.5@3659.43,275 v1(3710,275) ; v1(3823,226.89) 3826.11,230 R111.2@3878.5,230 ; v1(3823,305.63) 3838.63,290 D61.2@3863.74,290 ; D59.2@4078.11,978.68 v1(4078.11,1008) ; 4134.93,2026.41 4128.49,2032.85 4128.49,2175.89 4134.93,2182.33 4214.83,2182.33 C119.2@4233.11,2164.05 4236.81,2167.76 v1(4269.72,2167.76) U15.4@4306.5,2167.76 ; D58.2@4168.11,978.68 v1(4168.11,1008) ; D57.2@4258.11,978.68 v1(4258.11,1008) ; R112.2@4315,100.32 v1(4347.68,100.32) ; D56.2@4348.11,978.68 v1(4348.11,1008) ; v1(4416.5,2950.87) L12.1@4416.5,2989.37 ; C117.2@4553.11,2114.69 4553.11,2044.37 v1(4561.85,2035.63) ; D27.2@4583,2884.05 v1(4583,2913.37) ; D26.2@4638,2884.05 v1(4638,2913.37) ; v1(4684,1340) 4695,1340 4715,1320 C161.2@4785.32,1320 ; C75.2@4695,2884.05 v1(4695,2913.37) ; C158.2@4785.32,880 v1(4785.32,906) ; v1(4893.11,1726) Q2.2@4930.61,1726 ; C157.2@4909.68,880 v1(4950,880) ; C159.2@4909.68,1320 v1(4940,1320) ; v1(4920.11,1675) R138.2@4948.43,1675
  BOTTOM w20: 51.12,2964.05 J15.3@89.61,2964.05 ; 89.61,2925.55 J15.3@89.61,2964.05 ; 89.61,3002.55 J15.3@89.61,2964.05 ; 105.16,65.28 J24.25@151.53,65.28 ; 105.16,651.89 J24.26@151.53,651.89 151.53,613.39 ; 105.16,750.07 J28.25@151.53,750.07 ; 105.16,1336.69 J28.26@151.53,1336.69 ; 105.16,1434.87 J29.25@151.53,1434.87 ; 105.16,2021.48 J29.26@151.53,2021.48 ; 105.16,2705.28 J30.26@151.53,2705.28 ; 151.53,103.77 J24.25@151.53,65.28 ; 151.53,788.57 J28.25@151.53,750.07 ; 151.53,1298.19 J28.26@151.53,1336.69 ; 151.53,1375.18 J28.26@151.53,1336.69 ; 151.53,1396.37 J29.25@151.53,1434.87 ; 151.53,1473.36 J29.25@151.53,1434.87 ; 151.53,1982.99 J29.26@151.53,2021.48 ; 151.53,2059.98 J29.26@151.53,2021.48 ; 151.53,2080.17 J30.25@151.53,2118.66 ; 151.53,2157.16 J30.25@151.53,2118.66 ; 151.53,2666.78 J30.26@151.53,2705.28 ; 151.53,2743.77 J30.26@151.53,2705.28 ; 197.91,65.28 J24.25@151.53,65.28 ; 197.91,750.07 J28.25@151.53,750.07 ; 197.91,1434.87 J29.25@151.53,1434.87 ; 197.91,2021.48 J29.26@151.53,2021.48 ; 197.91,2118.66 J30.25@151.53,2118.66 ; 197.91,2705.28 J30.26@151.53,2705.28 ; 402.45,118.11 SS1.1@531.5,118.11 660.54,118.11 ; 402.45,2401.57 SS4.1@531.5,2401.57 ; 522.53,2743.11 J1.2@551.18,2743.11 ; 531.5,2272.52 SS4.1@531.5,2401.57 ; 531.5,2530.62 SS4.1@531.5,2401.57 ; 551.18,2684.91 J1.2@551.18,2743.11 ; 579.83,2743.11 J1.2@551.18,2743.11 ; 660.55,2401.57 SS4.1@531.5,2401.57 ; 731.13,2743.11 J1.3@759.78,2743.11 ; 759.78,2684.91 J1.3@759.78,2743.11 ; 759.78,2801.31 J1.3@759.78,2743.11 ; 788.43,2743.11 J1.3@759.78,2743.11 ; 826.74,283.46 J17.26@861.3,283.46 ; 826.74,362.2 J17.25@861.3,362.2 ; 861.3,318.03 J17.26@861.3,283.46 ; 861.3,327.64 J17.25@861.3,362.2 ; 895.86,283.46 J17.26@861.3,283.46 ; 895.86,362.2 J17.25@861.3,362.2 ; 1299.18,283.46 J17.14@1333.74,283.46 ; 1299.18,362.2 J17.13@1333.74,362.2 ; 1333.74,318.03 J17.14@1333.74,283.46 ; 1333.74,327.64 J17.13@1333.74,362.2 ; 1333.74,396.77 J17.13@1333.74,362.2 ; 1368.3,283.46 J17.14@1333.74,283.46 ; 1368.3,362.2 J17.13@1333.74,362.2 ; 1614.14,283.46 J17.6@1648.7,283.46 ; 1614.14,362.2 J17.5@1648.7,362.2 ; 1648.7,318.03 J17.6@1648.7,283.46 ; 1648.7,327.64 J17.5@1648.7,362.2 ; 1648.7,396.77 J17.5@1648.7,362.2 ; 1654.26,2933.07 J5.2@1684.88,2933.07 ; 1683.26,283.46 J17.6@1648.7,283.46 ; 1683.26,362.2 J17.5@1648.7,362.2 ; 1684.88,2886.7 J5.2@1684.88,2933.07 ; 1692.88,283.46 J17.4@1727.44,283.46 ; 1715.5,2933.07 J5.2@1684.88,2933.07 ; 1727.44,318.03 J17.4@1727.44,283.46 ; 1762,283.46 J17.4@1727.44,283.46 ; 1911.42,149.61 J18.31@1949.92,149.61 ; 1949.92,103.23 J18.31@1949.92,149.61 ; 1949.92,195.98 J18.31@1949.92,149.61 ; 2651.58,149.61 J18.32@2690.08,149.61 ; 2690.08,103.23 J18.32@2690.08,149.61 ; 2690.08,195.98 J18.32@2690.08,149.61 ; 2728.57,149.61 J18.32@2690.08,149.61 ; 2832.4,2644.5 J9.4@2861.05,2644.5 2889.71,2644.5 ; 2970.19,2585.45 J9.7@2998.85,2585.45 ; 2998.85,2556.79 J9.7@2998.85,2585.45 ; 2998.85,2614.11 J9.7@2998.85,2585.45 ; 3027.51,2585.45 J9.7@2998.85,2585.45 ; 3381.5,3020.55 J11.2@3420,3020.55 ; 3420,2982.05 J11.2@3420,3020.55 ; 3420,3059.05 J11.2@3420,3020.55 ; 3458.5,3020.55 J11.2@3420,3020.55 ; 3737.41,545 J32.4@3766.06,545 ; 3737.41,810 J16.4@3766.06,810 ; 3766.06,516.34 J32.4@3766.06,545 ; 3766.06,573.66 J32.4@3766.06,545 ; 3766.06,781.34 J16.4@3766.06,810 ; 3766.06,838.66 J16.4@3766.06,810 ; 3766.3,2696.85 J12.4@3804.8,2696.85 ; 3794.72,545 J32.4@3766.06,545 ; 3794.72,810 J16.4@3766.06,810 ; 3804.8,2658.35 J12.4@3804.8,2696.85 ; 3804.8,2735.35 J12.4@3804.8,2696.85 ; 3843.3,2696.85 J12.4@3804.8,2696.85 ; 4151.11,545 J35.4@4179.77,545 ; 4179.77,516.34 J35.4@4179.77,545 ; 4179.77,573.66 J35.4@4179.77,545 ; 4208.42,545 J35.4@4179.77,545 ; 4472.44,2658.35 J13.4@4472.44,2696.85 4510.94,2696.85 ; 4486.07,810 J27.7@4514.73,810 ; 4514.73,781.34 J27.7@4514.73,810 ; 4514.73,838.66 J27.7@4514.73,810 ; 4543.38,810 J27.7@4514.73,810 ; 4564.81,545 J36.4@4593.47,545 ; 4564.81,810 J27.8@4593.47,810 ; 4593.47,516.34 J36.4@4593.47,545 ; 4593.47,573.66 J36.4@4593.47,545 ; 4593.47,781.34 J27.8@4593.47,810 ; 4593.47,838.66 J27.8@4593.47,810 ; 4622.12,810 J27.8@4593.47,810 ; 4733.16,118.11 SS2.1@4862.2,118.11 ; 4733.16,2401.57 SS3.1@4862.21,2401.57 ; 4813.39,2184.57 J23.2@4838.11,2184.57 ; 4838.11,2209.29 J23.2@4838.11,2184.57 ; 4862.2,247.16 SS2.1@4862.2,118.11 ; 4862.21,2272.52 SS3.1@4862.21,2401.57 ; 4862.21,2530.62 SS3.1@4862.21,2401.57 ; 4862.83,2184.57 J23.2@4838.11,2184.57 ; 4948.24,2189.53 J25.2@4975.91,2189.53 ; 4975.91,2217.2 J25.2@4975.91,2189.53 ; 4991.25,118.11 SS2.1@4862.2,118.11 ; 4991.26,2401.57 SS3.1@4862.21,2401.57 ; 5003.58,2189.53 J25.2@4975.91,2189.53
  other v1: 334.53,31 784.53,31 934.53,31 1084.53,31 1234.53,31 1384.53,31 1534.53,31 1684.53,31 1834.53,31 1984.53,31 2134.53,31 2284.53,31 2434.53,31 2734.53,31 2884.53,31 3034.53,31 3184.53,31 3484.53,31 3634.53,31 3934.53,31 4084.53,31 4384.53,31 4534.53,31 3851.52,65 3890.89,65 3930.26,65 3969.63,65 378.74,70.06 3678.74,70.06 5067.43,78.74 2010.87,91.34 2459.74,97.11 2499.11,97.11 2538.48,97.11 4387.05,100.32 4426.42,100.32 4465.79,100.32 4505.16,100.32 4544.53,100.32 378.74,109.42 53.71,132.21 93.08,132.21 132.45,132.21 2757.11,137.15 2796.48,137.15 2224.01,139.96 4376.61,166.26 4415.98,166.26 4455.35,166.26 4494.72,166.26 4534.09,166.26 4573.46,166.26 4612.83,166.26 848,168 887.37,168 926.74,168 966.11,168 1005.48,168 1044.85,168 1084.22,168 1123.59,168 1162.96,168 53.71,171.57 93.08,171.57 132.45,171.57 3086.77,177.26 4612.83,205.63 2600,210 53.71,210.94 93.08,210.94 132.45,210.94 2073.93,210.93 2132.99,210.93 2192.04,210.93 2251.1,210.93 2312,211 2367,211 2546.37,210.93 2717.74,215.89 2811.18,216.63 2850.55,216.63 2889.92,216.63 2968.66,216.63 3086.77,216.63 4133.63,225 5067.43,228.74 1868,233.52 4355.35,245 4405.35,245 4652.2,245 1868,272.89 4766.26,296 59,307 1868,312.26 3710,314.37 4191,316 4230.37,316 4269.74,316 4766.26,335.37 214,348 144,350 1868,351.63 31,356.08 5067.43,378.74 1868,391 2886,401 3893,409 3932.37,409 4012.28,409 4091.02,409 4189,409 4228.37,409 4267.74,409 4307.11,409 4346.48,409 4385.85,409 4425.22,409 419,421 133,431 3339.37,449.68 59,460 1559,470 1708,471 1815,471 1241,479 618,494 800,494 891,494 31,506.08 1334.37,511.26 1373.74,511.26 1413.11,511.26 1452.48,511.26 5067.43,528.74 1334.37,550.63 1373.74,550.63 1413.11,550.63 1452.48,550.63 766,578 805.37,578 515,590.63 407.72,602.05 97,603 4921.58,615.95 4960.95,615.95 5000.32,615.95 2949,618 3050.75,618.35 3090.12,618.35 1929,621 687.63,623.29 1837,626 1345,630 1691,630 1583,637 1507.5,637.76 407.72,641.42 2949,657.37 1776,667 1929,667 950.53,670.63 989.9,670.63 1029.27,670.63 1507.5,677.13 1639,677 5067.43,678.74 3262.31,681.06 3362.86,681.06 687,695 1929,707 911.16,710 950.53,710 989.9,710 1029.27,710 1361,710 1776,714 1507.5,716.5 3262.31,720.43 3362.86,720.43 3631,738 3670.37,738 3709.74,738 3749.11,738 686,749 911.16,749.37 950.53,749.37 989.9,749.37 802,750 4696,750 3362.86,759.8 2485.26,778 2524.63,778 2564,778 1502.41,779.66 1572.41,779.66 1893,780.52 1766,782 1838,781.52 911.16,788.74 950.53,788.74 989.9,788.74 1029.27,788.74 1361,789 3362.86,799.17 1707,804.15 54.52,817 93.89,817 133.26,817 212,817 2485.26,817.37 2524.63,817.37 2564,817.37 1643,819 1893,819.89 1766,821.37 1838,820.89 5067.43,828.74 3362.86,838.54 1555,839.9 1707,843.52 1893,859.26 1838,860.26 855,861 1766,860.74 1645,877.26 1474,879 1707,882.89 4476.51,893.89 651,897 1893,898.63 1766,900.11 1838,899.63 54,911 1645,916.63 1707,922.26 4476.51,933.26 1475,935 1893,938 1766,939.48 1838,939 212,944.17 4641.97,946.77 130,950 31,956.08 1645,956 3262.31,956.65 1707,961.63 559.37,970.63 4476.51,972.63 5067.43,978.74 1555,981.63 4681.34,986.14 4760.08,986.14 4799.45,986.14 1645,1001 1707,1001 480.63,1010 559.37,1010 112,1016 212,1033.54 480.63,1049.37 520,1049.37 559.37,1049.37 1893,1052.78 1707,1075.63 1893,1092.15 1707,1115 1893,1131.52 1280.11,1138 1893,1170.89 1562.26,1178 4875,1185.63 1162,1188 1201.37,1188 1240.74,1188 4535.63,1192.99 3748.2,1207.37 3866.31,1207.37 1893,1210.26 1320,1220.26 4875,1225 2579,1229 2629,1229 2052,1236.4 2102,1236.4 3748.2,1246.74 3826.94,1246.74 3866.31,1246.74 1893,1249.63 407.72,1251.63 31,1256.08 4410.39,1270.2 4575,1271.73 5067.43,1278.74 3506.48,1286 1844,1289 1893,1289 1601,1290 1718,1290 1320,1299 2578,1305 2628,1305 1201,1327 1844,1349 1893,1349 1541.79,1350.53 1581.15,1350.53 1620.53,1350.53 1717,1351 5000.32,1359.69 3458.28,1366.42 3497.65,1366.42 4684,1379.37 31,1406.08 1716,1415.63 1844,1416.63 1892,1416.63 2578,1428 2628,1428 4641.97,1429.21 5067.43,1428.74 1716,1455 1594.37,1456.48 1633.74,1456.48 1844,1456 1892,1456 2024,1462 4641.97,1468.58 4681.34,1468.58 979,1500 1092,1500 93.08,1501.8 132.45,1501.8 2107,1511 2024,1512 3946.63,1523 93.08,1541.17 132.45,1541.17 31,1556.08 2107,1561 2024,1562 1595,1567 535,1575 574.37,1575 93.08,1580.54 132.45,1580.54 171.82,1580.54 2107,1611 2024,1612 535,1614.37 574.37,1614.37 93.08,1619.91 132.45,1619.91 171.82,1619.91 3255,1649 4487.11,1649.37 1842,1652.89 2107,1661 2024,1662 1594.37,1665.49 1717,1666 4681.11,1673.26 93.08,1678.96 1286.81,1680.63 1326.18,1680.63 1365.55,1680.63 4487.11,1688.74 4526.48,1688.74 4605.22,1688.74 1842,1692.26 31,1706.08 2107,1711 2024,1712 4681.11,1712.63 93.08,1718.33 1011.22,1720 1050.59,1720 1247.44,1720 1286.81,1720 321.89,1725 3892.8,1727.69 5067.43,1728.74 1842,1731.63 2650,1739 1594.37,1739.94 4681.11,1752 814.37,1759.37 1011.22,1759.37 1050.59,1759.37 1247.44,1759.37 1286.81,1759.37 1469,1759 595,1761.37 2107,1761 2024,1762 321.89,1764.37 1685.84,1771 1842,1771 1361,1775 2650,1789 1561.26,1790 1600.63,1790 1640,1790 814.37,1798.74 1050.59,1798.74 1286.81,1798.74 321.89,1803.74 2107,1811 2024,1812 4343.11,1818.82 123,1823 4681.11,1828 814.37,1838.11 1050.59,1838.11 1286.81,1838.11 595,1840.11 3754.11,1843.63 1541.79,1846.24 1599.89,1853 1639.26,1853 1678.63,1853 1718,1853 814.37,1877.48 971.85,1877.48 1011.22,1877.48 1050.59,1877.48 1286.81,1877.48 3497.43,1878.48 516.26,1879.48 555.63,1879.48 595,1879.48 5067.43,1878.74 1469,1881 3754.11,1883 3716.48,1905.32 132.45,1915.18 171.82,1915.18 1566.79,1917.46 1606.15,1917.46 1716.91,1948 1804,1948.26 132.45,1954.55 171.82,1954.55 1588,1958 1365,1985 1716.91,1987.37 1804,1987.63 3025,1992 3726,1996 4142.32,2002.32 4181.69,2002.32 4221.06,2002.32 4260.43,2002.32 31,2006.08 2900,2009 4712.48,2020 4751.85,2020 4791.22,2020 4830.59,2020 4869.96,2020 4909.33,2020 1594.37,2023.41 1716.91,2026.74 1804,2027 2084,2027 2620,2031 4260.43,2041.69 4299.8,2041.69 4339.17,2041.69 4378.54,2041.69 70.06,2046.05 1716.91,2066.11 635.67,2079.92 852.52,2079.92 1364,2085 3598.74,2084.56 3638.11,2084.56 1255,2090.63 1716.91,2105.48 3087.43,2112.23 992.26,2114.26 1076,2114.26 556.93,2119.29 596.3,2119.29 635.67,2119.29 773.78,2119.29 813.15,2119.29 852.52,2119.29 1805,2118.52 3598.74,2123.93 3638.11,2123.93 3875.11,2129 1255,2130 3810,2132 1716.91,2144.85 2004,2147 2043.37,2147 2082.74,2147 1036.63,2153.63 31,2156.08 1805,2157.89 413.82,2158.66 596.3,2158.66 813.15,2158.66 852.52,2158.66 1365,2164 5067.43,2178.74 3712.11,2182 1716.91,2184.22 1805,2197.26 813.15,2198.03 3418.74,2200.77 3536.85,2200.77 1365,2203.37 3982.48,2210 1036.63,2232.37 1283,2233 1634,2233 3719.28,2235 3753.14,2235 852.52,2237.4 1805,2236.63 1510,2260 4949.63,2262.88 1036.63,2271.74 1685,2275 1335,2276 1805,2276 2002,2276.26 675.04,2276.77 852.52,2276.77 2202.29,2294.26 4568,2304 31,2306.08 1060.63,2307 1100,2307 1160,2307 655.67,2316.14 695.04,2316.14 852.52,2316.14 2002,2315.63 1549,2321 1588.37,2321 5067.43,2328.74 1798,2343 2002,2355 4500,2367 3178.74,2372 3296.85,2372 3336.22,2372 1374,2374 1413.37,2374 201,2391 4311.11,2391 3538.11,2397.74 3577.48,2397.74 4498.63,2416 4538,2416 4577.37,2416 3494,2425 3724.37,2426 4384.41,2435.9 3724.37,2465.37 2721,2471 2760.37,2471 2799.74,2471 4384.41,2475.27 5067.43,2478.74 1584.05,2485.32 1623.42,2485.32 1662.79,2485.32 4384.41,2514.64 4455.11,2515 4494.48,2515 1584.05,2524.69 1623.42,2524.69 1662.79,2524.69 30.68,2530.42 960.44,2530.59 999.81,2530.59 1137.34,2550 1370,2559 960.44,2569.96 999.81,2569.96 1471,2586 31,2606.08 921.07,2609.33 960.44,2609.33 999.81,2609.33 5067.43,2628.74 1701.26,2630.37 1615,2636 802.96,2648.7 842.33,2648.7 174.34,2658.03 3524,2658.37 1780,2669.74 1615,2675.37 842.33,2688.07 3524,2697.74 1780,2709.11 1615,2714.74 842.33,2727.44 3371.26,2746.37 3410.63,2746.37 1615,2754.11 31,2756.08 2856.89,2757.63 2896.26,2757.63 2935.63,2757.63 2975,2757.63 3014.37,2757.63 3053.74,2757.63 3093.11,2757.63 5067.43,2778.74 1962,2784 810,2800 1962,2823.37 810,2839.37 849.37,2839.37 2182.37,2850 849.37,2878.74 715.87,2897.5 31,2906.08 849.37,2918.11 1967,2928.74 5067.43,2928.74 2935.63,2930.94 676.5,2936.87 715.87,2936.87 4455.87,2950.87 4495.24,2950.87 849.37,2957.48 2661.26,2963 2700.63,2963 2104.37,2969.37 2661.26,3002.37 2700.63,3002.37 3240,3011.37 62,3016.37 3145,3016.74 927.93,3030.98 5037.6,3075.75 185.91,3079.24 335.91,3079.24 485.91,3079.24 635.91,3079.24 1587.64,3079.24 1887.64,3079.24 2187.64,3079.24 2337.64,3079.24 2487.64,3079.24 2787.64,3079.24 2937.64,3079.24 3087.64,3079.24 3237.64,3079.24 3387.64,3079.24 3537.64,3079.24 3687.64,3079.24 3837.64,3079.24 3987.64,3079.24 4137.64,3079.24 4287.64,3079.24 4437.64,3079.24 4587.64,3079.24 4737.64,3079.24 4887.64,3079.24
GPIO0_C0: J3.38 R248.1 R253.1 | length 2353.1
  TOP w6.8: J3.38@3310.59,1917.28 3377.28,1917.28 3432.4,1972.4 3432.4,2020.23 v1(3432.77,2020.6)
  BOTTOM w6.8: v1(3432.77,2020.6) 3774.51,2020.6 3788.11,2007 3788.11,1958.89 3802,1945 3886,1945 3898,1933 3898,1909 3919,1888 4545.11,1888 4642.11,1791 4642.11,1616.11 4583,1557 4583,1302 4600,1285 4600,1115.32 R253.1@4635.32,1080 4674.68,1119.36 R248.1@4674.68,1120
GPIO0_C1: J3.39 R255.1 R257.1 | length 2216.2
  TOP w6.8: J3.39@3310.59,1952.72 3378.8,1952.72 3393.4,1967.32 v1(3393.4,2020.6)
  BOTTOM w6.8: v1(3393.4,2020.6) 3412.8,2040 3794.51,2040 3808.11,2026.4 3808.11,1998 3821.11,1985 3895,1985 3913,1967 3913,1920.01 3931.01,1902 4589.11,1902 4661.37,1829.74 4661.37,1571.37 4649,1559 4613.6,1559 4600,1545.4 4600,1414.18 4635.32,1378.87 R255.1@4635.32,1280 4635.32,1279.36 R257.1@4674.68,1240
GPIO0_C6: J3.43 R241.1 R242.1 | length 3337.4
  TOP w6.8: v1(3254,2094) 3254.45,2094.45 J3.43@3310.59,2094.45
  BOTTOM w6.8: v1(3254,2094) 3232,2072 3232,2042 3265,2009 3265,1900 3306.49,1858.51 3604.11,1858.51 3617.71,1844.91 3617.71,1813 3630.71,1800 3769,1800 3795,1774 3917,1774 3942,1749 4116,1749 4160,1793 4301,1793 4347,1747 4547,1747 4583,1711 4583,1602 4551,1570 4551,1317.16 4498,1264.16 4498,963 4535,926 4658,926 4675,909 4675,570 4691.2,553.8 4888.48,553.8 R241.1@4909.68,575 R242.1@4950.32,575
GPIO0_C7: J3.44 R243.1 R244.1 | length 2859.4
  TOP w6.8: J3.44@3310.59,2129.88 3354.12,2129.88 3367.17,2116.83 v1(3367.17,2094.9)
  BOTTOM w6.8: v1(3367.17,2094.9) 3367.17,1987.6 3380.77,1974 3754.51,1974 3768.11,1960.4 3768.11,1916.6 3781.71,1903 3878,1903 3910,1871 4537.11,1871 4627,1781.11 4627,1623 4570.2,1566.2 4570.2,1309.2 4516,1255 4516,985 4534.26,966.74 4877.94,966.74 R243.1@4909.68,935 R244.1@4950.32,935
GPIO0C0: R253.2 R254.1 | length 414.5
  BOTTOM w6.8: R253.2@4674.68,1080 4674.68,1035.32 4685,1025 5005,1025 5029.68,1000.32 R254.1@5030,1000.32
GPIO0C1: R255.2 R256.1 | length 525.9
  BOTTOM w6.8: R255.2@4674.68,1280 4660,1294.68 4660,1385 4680,1405 5015,1405 5030,1390 R256.1@5030,1359.68
GPIO0C6: R242.2 R249.1 | length 40.5
  BOTTOM w6.8: R242.2@4989.68,575 4990,575.32 R249.1@5030,575.32
GPIO0C7: R244.2 R250.1 | length 40.5
  BOTTOM w6.8: R244.2@4989.68,935 4990,934.68 R250.1@5030,934.68
HP_BUTTON_DET: C40.1 J3.33 R26.2 R29.1 | length 4317.9
  TOP w6.8: J3.33@3310.59,1740.12 3377.72,1740.12 3389.6,1752 3389.6,1861.86 v1(3405.65,1877.91)
  ART03 w6.3: v1(2182.37,2889.37) 2795.63,2889.37 2840,2845 2948,2845 3017.7,2914.7 3755.3,2914.7 3783,2887 3783,2767.39 3732.7,2717.09 3732.7,2524 3716.7,2508 3413.61,2508 3401,2495.39 3401,2381 3374,2354 2986.88,2354 2974.28,2341.4 2974.28,2152.72 2989,2138 2989,1890.51 3001.6,1877.91 v1(3405.65,1877.91)
  BOTTOM w6.8: R26.2@2034.68,2809.37 C40.1@2075.32,2809.37 ; R29.1@2075.32,2849.37 C40.1@2075.32,2809.37 ; v1(2182.37,2889.37) 2162.4,2869.4 2162.4,2801.33 2149.24,2788.17 2096.52,2788.17 C40.1@2075.32,2809.37
HP_PLUG_IN_DET: J3.196 R36.2 | length 3414.4
  TOP w6.8: J3.196@3090.12,527.52 v1(3090.12,578.98)
  ART03 w6.3: v1(2065,2929.37) 2065,2879.37 2075,2869.37 2633,2869.37 2657,2845.37 2657,2428.97 2669.6,2416.37 2821,2416.37 2835,2402.37 2835,591.58 2847.6,578.98 v1(3090.12,578.98)
  BOTTOM w6.8: R36.2@2034.68,2929.37 v1(2065,2929.37)
HP_SNS: J3.22 R38.2 | length 2725
  TOP w10: v1(3262.21,1350.42) 3262.28,1350.35 J3.22@3310.59,1350.35
  ART03 w10: v1(1961.94,2543.69) 1961.94,2069.06 2062.63,1968.37 v1(2062.63,1336.4)
  BOTTOM w10: R38.2@1780,2559.69 1804.69,2535 1835,2535 1865,2565 1940.63,2565 v1(1961.94,2543.69) ; v1(2062.63,1336.4) 2087.23,1361 3251.63,1361 v1(3262.21,1350.42)
HPL_OUT: C34.1 J3.21 R33.2 | length 7011.6
  TOP w10: v1(3262.21,1311.05) 3266.09,1314.92 J3.21@3310.59,1314.92
  ART03 w10: v1(2001.31,2543.69) 1977.94,2520.32 1977.94,2079.06 2078.63,1978.37 2078.63,1359.77 v1(2102,1336.4)
  ART04 w10: v1(623.74,860) 623.74,808.74 580,765 282,765 262,785 262,1394 232,1424 232,2564 252,2584 674,2584 700,2558 700,2449 720,2429 1880,2429 1895,2444 1895,2553 1910,2568 1977,2568 v1(2001.31,2543.69)
  BOTTOM w10: C34.1@610,895.32 610,873.74 v1(623.74,860) ; R33.2@1820,2559.69 1842.31,2582 1963,2582 v1(2001.31,2543.69) ; v1(2102,1336.4) 2110.6,1345 3228.26,1345 v1(3262.21,1311.05)
HPR_OUT: C46.1 J3.23 R34.2 | length 5569.7
  TOP w10: v1(3262.21,1389.79) 3266.21,1385.79 J3.23@3310.59,1385.79
  ART03 w10: v1(1922.57,2543.69) 1945.94,2520.32 1945.94,2060.06 2046.63,1959.37 2046.63,1359.77 v1(2023.26,1336.4)
  ART04 w10: v1(361.26,1882.48) 277,1882.48 250,1909.48 250,2544 270,2564 661,2564 681,2544 681,2426 701,2406 1902.57,2406 1922.57,2426 v1(1922.57,2543.69)
  BOTTOM w10: v1(361.26,1882.48) 361.26,1813.42 C46.1@370,1804.68 ; R34.2@1740,2559.69 1781.69,2518 1845,2518 1870.69,2543.69 v1(1922.57,2543.69) ; v1(2023.26,1336.4) 2064.21,1377.35 3249.78,1377.35 v1(3262.21,1389.79)
I2C0_SCL: J3.194 J24.6 U15.6 U17.22 | length 7996.1
  TOP w6.8: U17.22@883.86,1225.43 1024.76,1225.43 1042.37,1207.82 v1(1042.37,1130.37) ; J3.194@3019.25,527.52 3019.25,626.4 3032.85,640 3173.25,640 3186.85,653.6 v1(3186.85,1948)
  ART03 w6.3: v1(3186.85,1948) 3211,1972.15 3254.15,1972.15 3271,1989 3271,2067 3282.75,2078.75 3581.71,2078.75 3592.05,2068.41 3674.41,2068.41 3756,2150 3907,2150 3924,2167 3924,2234 3941,2251 4189.4,2251 4202,2238.4 4202,2158.6 4215.6,2145 4438.03,2145 v1(4445.85,2152.82)
  BOTTOM w6.8: J24.6@257.91,486.54 138.46,486.54 112,513 64.8,513 58,519.8 58,690.62 75.17,707.8 197,707.8 342,852.8 342,1069.4 355.6,1083 625,1083 647.4,1060.6 907,1060.6 913.71,1067.31 913.71,1103.71 923,1113 958,1113 996,1151 1021.74,1151 v1(1042.37,1130.37) 1096.4,1130.37 1110,1143.97 1110,1196.37 1134.63,1221 1214,1221 1282,1289 1282,1469 1303,1490 1536,1490 1567,1521 1935.2,1521 1942,1527.8 1942,1846 1979,1883 3173,1883 3186.85,1896.85 v1(3186.85,1948) ; v1(4445.85,2152.82) 4456.51,2142.16 U15.6@4479.72,2142.16
I2C0_SDA: J3.193 J24.5 U15.5 U17.23 | length 8095.6
  TOP w6.8: U17.23@883.86,1199.84 989.4,1199.84 1003,1186.24 v1(1003,1130.37) ; J3.193@2983.82,527.52 2983.82,646.4 2997.42,660 3148.3,660 3149.6,661.94 3164,676.35 3164,1969.52 v1(3186.85,1992.37)
  ART03 w6.3: v1(3186.85,1992.37) 3160,2019.22 3160,2169.4 3172.6,2182 3627,2182 3700,2255 3765,2255 3810,2300 4208.4,2300 4221,2287.4 4221,2212 4240.81,2192.19 v1(4445.85,2192.19)
  BOTTOM w6.8: J24.5@257.91,506.22 138.78,506.22 116,529 81.28,529 73.68,536.6 73.68,681.4 87.28,695 210,695 360,845 360,1056.6 373.6,1070.2 617.8,1070.2 640.2,1047.8 946.28,1047.8 953.08,1054.6 953.08,1093.2 959.88,1100 972.63,1100 v1(1003,1130.37) 1028.37,1105 1116.4,1105 1130,1118.6 1130,1189 1149,1208 1224,1208 1298,1282 1298,1452 1318,1472 1538,1472 1568,1502 1955.4,1502 1964,1510.6 1964,1841.13 1986.87,1864 3187,1864 3206.25,1883.25 3206.25,1972.97 v1(3186.85,1992.37) ; v1(4445.85,2192.19) 4445.85,2180.15 4458.24,2167.76 U15.5@4479.72,2167.76
I2C1_SCL_M1: J3.57 J18.9 J19.4 J28.6 R74.1 R174.2 | length 7170.7
  TOP w6.8: v1(171.82,1210.7) 171.82,1093 153,1074.18 153,784 168,769 168,599 153,584 v1(153,565.28) 153,418.8 166.6,405.2 J19.4@330.71,405.2 ; v1(1295,630) 1295,620.32 R74.1@1264.68,590 1264.68,438.6 1278.28,425 1895.4,425 1909,411.4 1909,244.8 1922.6,231.2 2383.8,231.2 2443.44,171.56 v1(2467.63,171.56) 2487.03,152.16 2565.2,152.16 2580,166.96 2580,355.31 v1(2635,410.31) ; v1(2731.75,2255.17) 3005.65,2255.17 3019.25,2268.77 J3.57@3019.25,2421.22
  ART03 w6.3: v1(2635,410.31) 2719.15,410.31 2731.75,422.91 v1(2731.75,2255.17)
  BOTTOM w6.8: v1(153,565.28) 172.97,545.31 210.31,545.31 222.92,557.92 222.92,657.92 392,827 532,827 546,813 742,813 756,827 1050,827 1068.2,808.8 1068.2,720.8 1081.8,707.2 1183.8,707.2 1200,691 1200,640 1210,630 v1(1295,630) ; v1(171.82,1210.7) 171.82,1184.93 185.42,1171.33 J28.6@257.91,1171.33 ; J18.9@2447.95,255.91 2447.95,191.24 v1(2467.63,171.56) ; R174.2@2730,2178.42 2730,2253.42 v1(2731.75,2255.17)
I2C1_SDA_M1: J3.58 J18.10 J19.5 J28.5 R75.1 R175.2 | length 7085.1
  TOP w6.8: v1(171.82,1250.07) 187.93,1250.07 203,1235 203,1084 182,1063 182,802 192.37,791.63 v1(192.37,565.28) 192.37,500.17 208.6,483.94 J19.5@330.71,483.94 ; R75.1@1264.68,630 1295,660.32 v1(1295,669.37) 1314.4,649.97 1314.4,456.6 1328,443 1911.4,443 1925,429.4 1925,257.6 1938.6,244 2393,244 2446.04,190.96 2487.6,190.96 v1(2507,171.56) 2552.4,171.56 2566,185.16 2566,380.68 v1(2635,449.68) ; v1(2691.75,2255.17) 2711.72,2275.14 2970.22,2275.14 2983.82,2288.74 J3.58@2983.82,2421.22
  ART03 w6.3: v1(2635,449.68) 2702.48,449.68 2715.08,462.28 2715.08,2231.84 v1(2691.75,2255.17)
  BOTTOM w6.8: v1(171.82,1250.07) 192.6,1229.29 192.6,1202.66 204.25,1191.02 J28.5@257.91,1191.02 ; v1(192.37,565.28) 210.12,583.03 210.12,663.22 386.9,840 541,840 554,827 735,827 749,841 1065,841 1081,825 1081,733.6 1094.6,720 1193,720 1215,698 1215,680 1225.63,669.37 v1(1295,669.37) ; J18.10@2428.26,255.91 2428.26,181.74 2458,152 2487.44,152 v1(2507,171.56) ; R175.2@2690,2178.42 2690,2253.42 v1(2691.75,2255.17)
I2C2_SCL_M1: J3.55 J29.6 R189.2 | length 4028.9
  TOP w6.8: v1(2651.75,2215.17) 3076.52,2215.17 3090.12,2228.77 J3.55@3090.12,2421.22
  ART03 w6.3: v1(321.89,1843.11) 352.11,1843.11 422.93,1913.93 902.4,1913.93 915,1901.33 915,1741.89 v1(893.11,1720)
  BOTTOM w6.8: J29.6@257.91,1856.13 308.87,1856.13 v1(321.89,1843.11) ; v1(893.11,1720) 893.11,1630.6 909.71,1614 1852.4,1614 1866,1627.6 1866,2220.97 1879.6,2234.57 2632.35,2234.57 v1(2651.75,2215.17) 2650,2213.42 R189.2@2650,2178.42
I2C2_SDA_M1: J3.56 J29.5 R190.2 | length 4082.4
  TOP w6.8: v1(2611.75,2215.17) 2631.58,2235 3041.09,2235 3054.68,2248.6 J3.56@3054.68,2421.22
  ART03 w6.3: v1(211.19,1875.81) 263.04,1823.96 352.96,1823.96 430,1901 864,1901 873.96,1891.04 873.96,1740.22 v1(853.74,1720)
  BOTTOM w6.8: v1(211.19,1875.81) J29.5@257.91,1875.81 ; v1(853.74,1720) 853.74,1616.26 871,1599 1869.4,1599 1883,1612.6 1883,2201.57 1896.6,2215.17 v1(2611.75,2215.17) 2610,2213.42 R190.2@2610,2178.42
I2C5_SCL_M1: J3.148 J30.6 R191.2 | length 4076.5
  TOP w6.8: J3.148@1416.89,677.13 v1(1468.13,677.13) 1468.2,677.13 1475,683.93 1475,740 1492,757 1585,757 1610,782 1610,1169.63 v1(1601.63,1178)
  ART03 w6.3: v1(174.34,2618.66) 194,2599 662.4,2599 675,2586.4 675,2473 699,2449 1406,2449 1475,2380 1758.4,2380 1775,2363.4 1775,1812 1792.3,1794.7 1792.3,1172.51 1776.8,1157 1622.63,1157 v1(1601.63,1178)
  BOTTOM w6.8: v1(174.34,2618.66) 156.6,2618.66 149,2611.06 149,2568 157.11,2559.89 183.11,2559.89 203.08,2539.92 J30.6@257.91,2539.92 ; R191.2@1429.68,676 1467,676 v1(1468.13,677.13)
